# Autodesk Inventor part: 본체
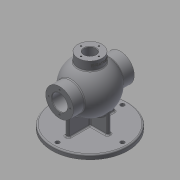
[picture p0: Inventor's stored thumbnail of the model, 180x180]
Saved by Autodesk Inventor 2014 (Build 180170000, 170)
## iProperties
Created: 2020-08
Part Number: 본체
Material: Generic
Document SubType Name: Modeling
Designer: kh
Density: 1 g/cm^3
Appearance: Default
Mass: 649.142 g
Surface Area: 1342.42 cm^2
Volume: 649.142 cm^3
Author: kh
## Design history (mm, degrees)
sketch "스케치1"
  geometry: L1 (-68, 85)-(68, 85); L2 (-68, 102.5)-(-68, 116); L3 (-68, 116)-(-42.988, 116); L4 (68, 102.5)-(68, 116); L5 (68, 116)-(42.988, 116); L6 (-68, 102.5)-(-39.278, 102.5); L7 (39.278, 102.5)-(50.25, 102.5); L8 (50.25, 102.5)-(50.25, 103.5); L9 (50.25, 103.5)-(52, 103.5); L10 (52, 103.5)-(52, 102.5); L11 (52, 102.5)-(68, 102.5); A1 r 43 centre (0, 85) between (39.278, 102.5) and (-39.278, 102.5); A2 r 53 centre (0, 85) between (42.988, 116) and (-42.988, 116); 2 further points
  constraints: 22 end point, 5 collinear, 4 point on circle, 3 parallel, 3 vertical alignment, 2 centre point, 2 coincident, 2 perpendicular, 2 point on line, 1 horizontal, 1 midpoint
  dimensions: "d0" = 85 distance from line of point (0, 0) L1; "d1" = 136 distance of L1.start L1.end; "d3" = 62 diameter of L3 L1; "d4" = 53 radius of A2; "d5" = 43 radius of A1; "d42" = 35 diameter of L6 L1; "d82" = 16 distance between parallel lines of L4 L10; "d83" = 1.75 distance of L8.end L9.end; "d84" = 37 diameter of L9 L1
revolve "회전1" sketch "스케치1" stored, may be unused: angle "d6" = 90 deg
sketch "스케치2"
  geometry: C1 r 85 at (0, 0); 1 further point
  constraints: 1 centre point, 1 coincident
  dimensions: "d7" = 170 diameter of C1
extrude "돌출1" join sketch "스케치2" distance "d8" = 10; taper "d9" = 0 deg
node "작업 평면1"
sketch "스케치3"
  geometry: C1 r 27 at (0, 0); 1 further point
  constraints: 1 centre point, 1 coincident
  dimensions: "d11" = 54 diameter of C1
extrude "돌출2" join sketch "스케치3" stored distance "d12" = 10; taper "d13" = 0 deg
hole "구멍1" diameter "d16" = 26; stored, may be unused: countersink angle "d20" = 90 deg, drill point angle "d22" = 118 deg; dims "d14" = 10, "d15" = 10, "d17" = 6, "d18" = 4, "d19" = 2, "d21" = 8
sketch "스케치4"
  geometry: L1 (-43, -4)-(43, -4); L2 (43, -4)-(43, 4); L3 (43, 4)-(-43, 4); L4 (-43, 4)-(-43, -4); L5 (-43, -4)-(43, 4); L6 (43, -4)-(-43, 4); 1 further point
  constraints: 12 end point, 2 midpoint, 2 parallel, 1 horizontal, 1 perpendicular
  dimensions: "d23" = 8 distance between parallel lines of L1 L3; "d24" = 86 distance between parallel lines of L4 L2
extrude "돌출3" join sketch "스케치4" stored distance "d25" = 10; taper "d26" = 0 deg
sketch "스케치5"
  geometry: L1 (52, 57.024)-(52, 0); L2 (-85, 0)-(85, 0) reference; 1 further point
  constraints: 2 end point, 1 point on line, 1 vertical
  dimensions: "d27" = 52 distance from line of L1 point (0, 0)
feature "리브1" sketch "스케치5" dims "d28" = 1, "d29" = 8, "d30" = 0, "d31" = 0, "d32" = 1, "d33" = 1
sketch "스케치6"
  geometry: A1 r 72.5 centre (0, 0) between (0, 72.5) and (0, -72.5); 3 further points
  constraints: 4 point on circle, 2 horizontal alignment, 2 vertical alignment, 1 centre point, 1 coincident
  dimensions: "d34" = 145 diameter of A1
hole "구멍2" sketch "스케치6" at (0, 72.5), (0, -72.5), (72.5, 0), (-72.5, 0) diameter "d35" = 9; stored, may be unused: countersink angle "d39" = 90 deg, drill point angle "d41" = 118 deg; dims "d36" = 6, "d37" = 4, "d38" = 2, "d40" = 8
sketch "스케치7"
  geometry: L1 (0, 0)-(0, 24); C1 r 17.5 at (0, 0) reference; 2 further points
  constraints: 2 end point, 1 coincident, 1 vertical
  dimensions: "d46" = 24 distance of L1.start L1.end
hole "구멍3" sketch "스케치7" at (0, 24) diameter "d47" = 3.242; stored, may be unused: countersink angle "d51" = 90 deg, drill point angle "d53" = 118 deg; dims "d48" = 12, "d49" = 4, "d50" = 2, "d52" = 15
sketch "스케치8"
  geometry: L1 (0, 0)-(0, 20); 1 further point
  constraints: 2 end point, 1 coincident, 1 vertical
  dimensions: "d57" = 20 distance of L1.start L1.end
hole "구멍4" sketch "스케치8" at (0, 20) diameter "d58" = 3.242; stored, may be unused: countersink angle "d62" = 90 deg, drill point angle "d64" = 118 deg; dims "d59" = 12, "d60" = 4, "d61" = 2, "d63" = 15
chamfer "모따기1" distance "d68" = 1; stored, may be unused: second distance "d69" = 2, angle "d70" = 45 deg
chamfer "모따기2" distance "d71" = 1; stored, may be unused: second distance "d72" = 2, angle "d73" = 45 deg
chamfer "모따기3" distance "d74" = 1; stored, may be unused: second distance "d75" = 2, angle "d76" = 45 deg
fillet "모깎기1" dims "d77" = 3
fillet "모깎기2" dims "d78" = 3
node "작업 평면2"
sketch "스케치9"
  geometry: L1 (-30.666, -4.561)-(30.666, -4.561); L2 (30.666, -4.561)-(30.666, -13.439); L3 (30.666, -13.439)-(-30.666, -13.439); L4 (-30.666, -13.439)-(-30.666, -4.561); L5 (-30.666, -4.561)-(30.666, -13.439); L6 (-27, 0)-(27, 0) reference; 3 further points
  constraints: 2 end point, 2 midpoint, 1 vertical alignment, 2 other
  dimensions: "d79" = 9 distance of point (0, 0) point (0, -9)
feature "엠보싱1" sketch "스케치9" dims "d0" = 85, "d1" = 136, "d3" = 62, "d4" = 53, "d5" = 43, "d42" = 35, "d80" = 0.5, "d81" = 0, "d82" = 16, "d83" = 1.75, "d84" = 37
node "솔리드1"
mirror "대칭1"
mirror "대칭2"
pattern_circular "원형 패턴1" dims angle "d55" = 360 deg
pattern_circular "원형 패턴2" dims angle "d66" = 360 deg
